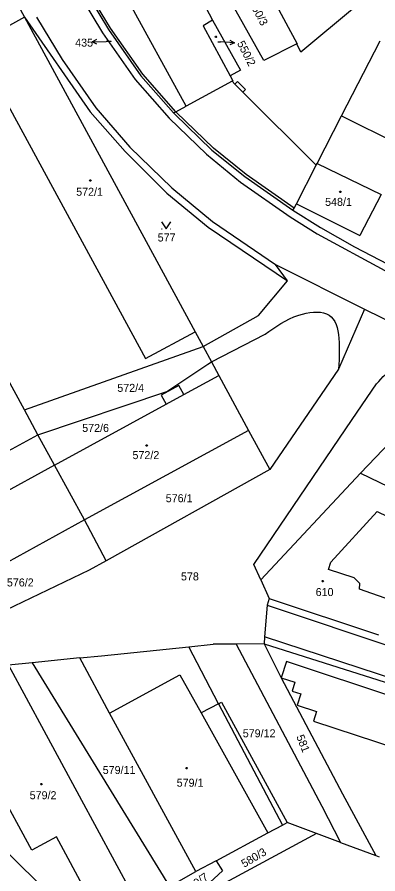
# Model space of a CAD drawing. Extents: x -621797 to -620972, y -1175539 to -1174697.
# Drawn here: x -621691.5 to -621614.9, y -1174979.5 to -1174797.6 of the extents above; entities that cross this region are included whole.
import ezdxf

# ---------------------------------------------------------------- set-up
doc = ezdxf.new("R2010")
doc.units = 0
for name, color, linetype in [('INZ mimo EON - nadz', 7, 'Continuous'), ('Rozvod plynu EON', 7, 'Continuous'), ('SDEL EON', 7, 'Continuous'), ('SDEL EON - popis', 7, 'Continuous'), ('Silnoproud EON', 7, 'Continuous'), ('Silnoproud EON - popis', 7, 'Continuous')]:
    doc.layers.add(name, color=color, linetype=linetype)

msp = doc.modelspace()

# ---------------------------------------------------------------- linework, layer by layer
at = {"layer": 'INZ mimo EON - nadz'}
for p, q in [((-621675.62, -1174802.822), (-621672.62, -1174802.77)), ((-621671.56, -1174802.75), (-621672.62, -1174802.77)), ((-621648.92, -1174802.83), (-621648.37, -1174802.86)), ((-621645.374, -1174803.023), (-621648.37, -1174802.86))]:
    msp.add_line(p, q, dxfattribs=at)
for points in [[(-621674.611, -1174803.304), (-621675.62, -1174802.822), (-621674.628, -1174802.304)], [(-621646.346, -1174802.469), (-621645.374, -1174803.023), (-621646.4, -1174803.468)]]:
    msp.add_lwpolyline(points, dxfattribs=at)
at = {"layer": 'Rozvod plynu EON'}
for points in [[(-621649.26, -1174801.64), (-621649.17, -1174801.79), (-621649.26, -1174801.94), (-621649.44, -1174801.94), (-621649.53, -1174801.79), (-621649.44, -1174801.64)], [(-621675.91, -1174832.13), (-621675.82, -1174832.28), (-621675.91, -1174832.43), (-621676.09, -1174832.43), (-621676.18, -1174832.28), (-621676.09, -1174832.13)], [(-621622.81, -1174834.55), (-621622.72, -1174834.7), (-621622.81, -1174834.85), (-621622.99, -1174834.85), (-621623.08, -1174834.7), (-621622.99, -1174834.55)], [(-621663.95, -1174888.42), (-621663.86, -1174888.57), (-621663.95, -1174888.72), (-621664.13, -1174888.72), (-621664.22, -1174888.57), (-621664.13, -1174888.42)], [(-621626.55, -1174917.2), (-621626.46, -1174917.35), (-621626.55, -1174917.5), (-621626.73, -1174917.5), (-621626.82, -1174917.35), (-621626.73, -1174917.2)], [(-621655.48, -1174956.89), (-621655.39, -1174957.04), (-621655.48, -1174957.19), (-621655.66, -1174957.19), (-621655.75, -1174957.04), (-621655.66, -1174956.89)], [(-621686.29, -1174960.32), (-621686.2, -1174960.47), (-621686.29, -1174960.62), (-621686.47, -1174960.62), (-621686.56, -1174960.47), (-621686.47, -1174960.32)]]:
    msp.add_lwpolyline(points, close=True, dxfattribs=at)
at = {"layer": 'SDEL EON'}
for p, q in [((-621660.87, -1174842.53), (-621660.77, -1174842.53)), ((-621659.07, -1174842.53), (-621658.97, -1174842.53))]:
    msp.add_line(p, q, dxfattribs=at)
msp.add_lwpolyline([(-621660.92, -1174841.03), (-621659.92, -1174842.53), (-621658.92, -1174841.03)], dxfattribs=at)
at = {"layer": 'SDEL EON - popis'}
for p, q in [((-621671.71, -1174799.96), (-621676.83, -1174791.49)), ((-621689.95, -1174797.61), (-621676.03, -1174817.69)), ((-621664.89, -1174809.7), (-621671.71, -1174799.96)), ((-621700.54, -1174803.38), (-621664.27, -1174870.06)), ((-621657.86, -1174817.67), (-621664.89, -1174809.7)), ((-621645.9, -1174811.21), (-621645.29, -1174811.82)), ((-621645.29, -1174811.82), (-621644.73, -1174811.26)), ((-621645.29, -1174811.82), (-621643.6, -1174813.5)), ((-621644.73, -1174811.26), (-621643.05, -1174812.95)), ((-621643.05, -1174812.95), (-621643.6, -1174813.5)), ((-621643.6, -1174813.5), (-621628.04, -1174829.02)), ((-621676.03, -1174817.69), (-621668.6, -1174826.13)), ((-621657.78, -1174817.76), (-621657.86, -1174817.67)), ((-621649.86, -1174825.44), (-621657.78, -1174817.76)), ((-621668.6, -1174826.13), (-621659.74, -1174834.96)), ((-621642.88, -1174831.01), (-621649.86, -1174825.44)), ((-621627.85, -1174828.65), (-621614.22, -1174835.26)), ((-621632.73, -1174838.15), (-621642.88, -1174831.01)), ((-621659.74, -1174834.96), (-621650.96, -1174842.17)), ((-621614.22, -1174835.26), (-621618.74, -1174843.99)), ((-621632.22, -1174837.21), (-621618.74, -1174843.99)), ((-621650.96, -1174842.17), (-621634.12, -1174853.6)), ((-621634.12, -1174853.6), (-621636.69, -1174850.15)), ((-621640.3, -1174860.93), (-621634.12, -1174853.6)), ((-621652.05, -1174867.51), (-621640.3, -1174860.93)), ((-621664.27, -1174870.06), (-621653.72, -1174864.43)), ((-621650.26, -1174870.81), (-621638.9, -1174864.93)), ((-621657.23, -1174875.8), (-621660.95, -1174877.84)), ((-621656.17, -1174877.73), (-621657.23, -1174875.8)), ((-621620.43, -1174883.05), (-621615.24, -1174875.44)), ((-621660.95, -1174877.84), (-621659.89, -1174879.77)), ((-621641.25, -1174913.84), (-621620.43, -1174883.05)), ((-621683.62, -1174892.74), (-621718.27, -1174911.66)), ((-621624.91, -1174913.3), (-621615.07, -1174902.56)), ((-621615.07, -1174902.56), (-621605.65, -1174907.25)), ((-621639.81, -1174917.04), (-621641.25, -1174913.84)), ((-621625.42, -1174914.87), (-621624.91, -1174913.3)), ((-621619.98, -1174916.66), (-621625.42, -1174914.87)), ((-621618.79, -1174917.81), (-621619.98, -1174916.66)), ((-621618.88, -1174919.05), (-621618.79, -1174917.81)), ((-621612.2, -1174921.39), (-621618.88, -1174919.05)), ((-621638.43, -1174922.48), (-621594.39, -1174937.13)), ((-621594.15, -1174943.9), (-621639.01, -1174929.15)), ((-621693.38, -1174935.2), (-621666.02, -1174985.69)), ((-621634.38, -1174934.4), (-621635.47, -1174937.86)), ((-621595.24, -1174947.37), (-621634.38, -1174934.4)), ((-621671.9, -1174945.35), (-621656.97, -1174937.23)), ((-621656.97, -1174937.23), (-621652.49, -1174945.31)), ((-621635.47, -1174937.86), (-621632.57, -1174938.78)), ((-621632.57, -1174938.78), (-621633.13, -1174940.68)), ((-621633.13, -1174940.68), (-621631.31, -1174941.24)), ((-621631.31, -1174941.24), (-621632.09, -1174943.66)), ((-621688.4, -1174974.48), (-621706.15, -1174942.05)), ((-621648.76, -1174943.36), (-621648.13, -1174943.03)), ((-621648.13, -1174943.03), (-621634.22, -1174968.59)), ((-621648.76, -1174943.36), (-621652.49, -1174945.31)), ((-621632.09, -1174943.66), (-621627.99, -1174945.05)), ((-621627.99, -1174945.05), (-621628.62, -1174947.05)), ((-621652.49, -1174945.31), (-621638.33, -1174970.8)), ((-621628.62, -1174947.05), (-621603.23, -1174955.42)), ((-621683.18, -1174971.62), (-621688.4, -1174974.48)), ((-621673.76, -1174989.11), (-621683.18, -1174971.62))]:
    msp.add_line(p, q, dxfattribs=at)
for points in [[(-621638.9, -1174864.93), (-621631.73, -1174860.89), (-621625.86, -1174860.58), (-621623.29, -1174872.33)], [(-621615.24, -1174875.44), (-621611.31, -1174871.61), (-621605.82, -1174868.33)]]:
    msp.add_spline(points, degree=3, dxfattribs=at)
at = {"layer": 'Silnoproud EON'}
for p, q in [((-621655.66, -1174816.48), (-621678.31, -1174775.2)), ((-621696.45, -1174785.61), (-621689.95, -1174797.61)), ((-621639.19, -1174806.8), (-621649.55, -1174788.17)), ((-621639.7, -1174789.11), (-621632.1, -1174803.25)), ((-621677.25, -1174791.74), (-621672.13, -1174800.21)), ((-621678.46, -1174792.52), (-621673.44, -1174800.94)), ((-621651.5, -1174795.55), (-621650.03, -1174798.25)), ((-621619.46, -1174795.23), (-621631.32, -1174805.02)), ((-621689.95, -1174797.61), (-621700.54, -1174803.38)), ((-621689.95, -1174797.61), (-621653.72, -1174864.43)), ((-621687.47, -1174797.58), (-621681.99, -1174806.59)), ((-621650.03, -1174798.25), (-621652.07, -1174799.47)), ((-621652.07, -1174799.47), (-621646.29, -1174810.07)), ((-621650.03, -1174798.25), (-621644.11, -1174808.88)), ((-621673.44, -1174800.94), (-621666.5, -1174810.81)), ((-621672.13, -1174800.21), (-621665.26, -1174810.03)), ((-621622.69, -1174818.56), (-621614.45, -1174802.6)), ((-621690, -1174880.99), (-621731.51, -1174804.52)), ((-621632.18, -1174803.29), (-621639.19, -1174806.8)), ((-621632.1, -1174803.25), (-621632.18, -1174803.29)), ((-621631.32, -1174805.02), (-621632.18, -1174803.29)), ((-621681.99, -1174806.59), (-621674.85, -1174816.82)), ((-621665.26, -1174810.03), (-621658.32, -1174817.92)), ((-621644.11, -1174808.88), (-621646.29, -1174810.07)), ((-621646.29, -1174810.07), (-621645.72, -1174811.12)), ((-621666.5, -1174810.81), (-621659.25, -1174819.07)), ((-621645.9, -1174811.21), (-621655.66, -1174816.48)), ((-621645.72, -1174811.12), (-621645.9, -1174811.21)), ((-621674.85, -1174816.82), (-621667.59, -1174825.18)), ((-621658.32, -1174817.92), (-621657.86, -1174817.67)), ((-621657.86, -1174817.67), (-621655.66, -1174816.48)), ((-621659.25, -1174819.07), (-621651.35, -1174826.68)), ((-621658.32, -1174817.92), (-621658.16, -1174818.1)), ((-621658.16, -1174818.1), (-621650.17, -1174825.83)), ((-621627.85, -1174828.65), (-621622.69, -1174818.56)), ((-621622.69, -1174818.56), (-621609.17, -1174825.28)), ((-621667.59, -1174825.18), (-621658.72, -1174833.86)), ((-621651.35, -1174826.68), (-621644.15, -1174832.61)), ((-621650.17, -1174825.83), (-621643.19, -1174831.4)), ((-621628.04, -1174829.02), (-621627.85, -1174828.65)), ((-621632.22, -1174837.21), (-621628.04, -1174829.02)), ((-621643.19, -1174831.4), (-621632.97, -1174838.58)), ((-621658.72, -1174833.86), (-621650.04, -1174840.99)), ((-621644.15, -1174832.61), (-621633.59, -1174839.98)), ((-621632.73, -1174838.15), (-621632.22, -1174837.21)), ((-621632.97, -1174838.58), (-621632.73, -1174838.15)), ((-621632.97, -1174838.58), (-621627.15, -1174842.29)), ((-621650.04, -1174840.99), (-621636.69, -1174850.15)), ((-621633.59, -1174839.98), (-621627.87, -1174843.57)), ((-621627.15, -1174842.29), (-621619.93, -1174846.35)), ((-621627.87, -1174843.57), (-621613.5, -1174851.4)), ((-621619.93, -1174846.35), (-621612.85, -1174850.03)), ((-621636.69, -1174850.15), (-621617.77, -1174859.61)), ((-621617.77, -1174859.61), (-621623.29, -1174872.33)), ((-621617.77, -1174859.61), (-621599.53, -1174868.58)), ((-621653.72, -1174864.43), (-621652.05, -1174867.51)), ((-621690, -1174880.99), (-621652.05, -1174867.51)), ((-621652.05, -1174867.51), (-621650.26, -1174870.81)), ((-621659.79, -1174877.1), (-621651.07, -1174871.28)), ((-621651.07, -1174871.28), (-621650.26, -1174870.81)), ((-621650.26, -1174870.81), (-621648.71, -1174873.66)), ((-621623.29, -1174872.33), (-621637.87, -1174893.66)), ((-621656.17, -1174877.73), (-621648.71, -1174873.66)), ((-621648.71, -1174873.66), (-621642.44, -1174885.34)), ((-621597.99, -1174872.64), (-621618.6, -1174894.42)), ((-621687.14, -1174886.26), (-621659.79, -1174877.1)), ((-621659.89, -1174879.77), (-621656.17, -1174877.73)), ((-621687.14, -1174886.26), (-621690, -1174880.99)), ((-621683.62, -1174892.74), (-621659.89, -1174879.77)), ((-621721.67, -1174905.13), (-621687.14, -1174886.26)), ((-621683.62, -1174892.74), (-621687.14, -1174886.26)), ((-621642.44, -1174885.34), (-621677.24, -1174904.34)), ((-621642.44, -1174885.34), (-621637.87, -1174893.66)), ((-621677.24, -1174904.34), (-621683.62, -1174892.74)), ((-621637.87, -1174893.66), (-621672.61, -1174913.02)), ((-621618.6, -1174894.42), (-621639.81, -1174917.04)), ((-621618.6, -1174894.42), (-621603.78, -1174901.63)), ((-621677.24, -1174904.34), (-621711.84, -1174923.39)), ((-621672.61, -1174913.02), (-621677.24, -1174904.34)), ((-621672.61, -1174913.02), (-621676.24, -1174915.04)), ((-621676.24, -1174915.04), (-621699.69, -1174926.23)), ((-621639.81, -1174917.04), (-621638, -1174921.06)), ((-621638, -1174921.06), (-621638.43, -1174922.48)), ((-621638, -1174921.06), (-621614.82, -1174928.75)), ((-621638.43, -1174922.48), (-621639.01, -1174929.15)), ((-621639.01, -1174929.15), (-621639.11, -1174930.68)), ((-621673.66, -1174933.18), (-621655.11, -1174931.28)), ((-621655.11, -1174931.28), (-621649.95, -1174930.75)), ((-621648.76, -1174943.36), (-621655.11, -1174931.28)), ((-621645.01, -1174930.71), (-621649.95, -1174930.75)), ((-621639.11, -1174930.68), (-621645.01, -1174930.71)), ((-621645.01, -1174930.71), (-621626.81, -1174965.11)), ((-621639.11, -1174930.68), (-621635.47, -1174937.86)), ((-621639.11, -1174930.68), (-621594.45, -1174944.82)), ((-621678.26, -1174933.65), (-621688.39, -1174934.69)), ((-621678.26, -1174933.65), (-621673.66, -1174933.18)), ((-621671.9, -1174945.35), (-621678.26, -1174933.65)), ((-621688.39, -1174934.69), (-621693.38, -1174935.2)), ((-621688.39, -1174934.69), (-621659.22, -1174982.2)), ((-621635.47, -1174937.86), (-621622.48, -1174962.47)), ((-621648.76, -1174943.36), (-621635.23, -1174969.13)), ((-621653.6, -1174979.01), (-621671.9, -1174945.35)), ((-621622.48, -1174962.47), (-621615.36, -1174975.63)), ((-621626.81, -1174965.11), (-621622.88, -1174972.82)), ((-621635.23, -1174969.13), (-621634.22, -1174968.59)), ((-621628, -1174970.91), (-621634.22, -1174968.59)), ((-621638.33, -1174970.8), (-621635.23, -1174969.13)), ((-621628, -1174970.91), (-621655.46, -1174985.74)), ((-621649.28, -1174976.7), (-621638.33, -1174970.8)), ((-621622.88, -1174972.82), (-621628, -1174970.91)), ((-621622.88, -1174972.82), (-621615.36, -1174975.63)), ((-621677.59, -1174990.81), (-621694.08, -1174974.46)), ((-621615.36, -1174975.63), (-621614.64, -1174975.9)), ((-621649.28, -1174976.7), (-621653.6, -1174979.01)), ((-621649.28, -1174976.7), (-621647.97, -1174978.87)), ((-621659.22, -1174982.2), (-621653.6, -1174979.01)), ((-621647.97, -1174978.87), (-621655.46, -1174985.74))]:
    msp.add_line(p, q, dxfattribs=at)

# ---------------------------------------------------------------- texts
at = {"layer": 'INZ mimo EON - nadz'}
msp.add_text('435', height=1.7, dxfattribs=at).set_placement((-621679.223, -1174803.86))
msp.add_text('550/2', height=1.7, rotation=297.02132, dxfattribs=at).set_placement((-621644.898, -1174803.149))
at = {"layer": 'Silnoproud EON - popis'}
for s, height, rotation, p in [('550/3', 1.7, 297.88076, (-621642.369, -1174794.57)), ('435', 0.1, 303.32386, (-621671.552, -1174802.762)), ('581', 1.7, 291.57822, (-621632.303, -1174950.341)), ('580/3', 1.7, 30.59595, (-621643.326, -1174978.219)), ('579/7', 1.7, 34.37747, (-621655.476, -1174983.77))]:
    msp.add_text(s, height=height, rotation=rotation, dxfattribs=at).set_placement(p)
for s, height, p in [('550/2', 0.1, (-621649.133, -1174802.83)), ('572/1', 1.7, (-621679.013, -1174835.52)), ('548/1', 1.7, (-621626.149, -1174837.67)), ('577', 1.7, (-621661.703, -1174845.23)), ('572/4', 1.7, (-621670.273, -1174877.16)), ('572/6', 1.7, (-621677.733, -1174885.67)), ('572/2', 1.7, (-621667.053, -1174891.43)), ('576/1', 1.7, (-621659.993, -1174900.59)), ('578', 1.7, (-621656.753, -1174917.19)), ('576/2', 1.7, (-621693.723, -1174918.47)), ('610', 1.7, (-621628.153, -1174920.51)), ('579/12', 1.7, (-621643.635, -1174950.5)), ('579/11', 1.7, (-621673.373, -1174958.29)), ('579/1', 1.7, (-621657.663, -1174960.99)), ('579/2', 1.7, (-621688.883, -1174963.65))]:
    msp.add_text(s, height=height, dxfattribs=at).set_placement(p)

doc.saveas('drawing.dxf')
